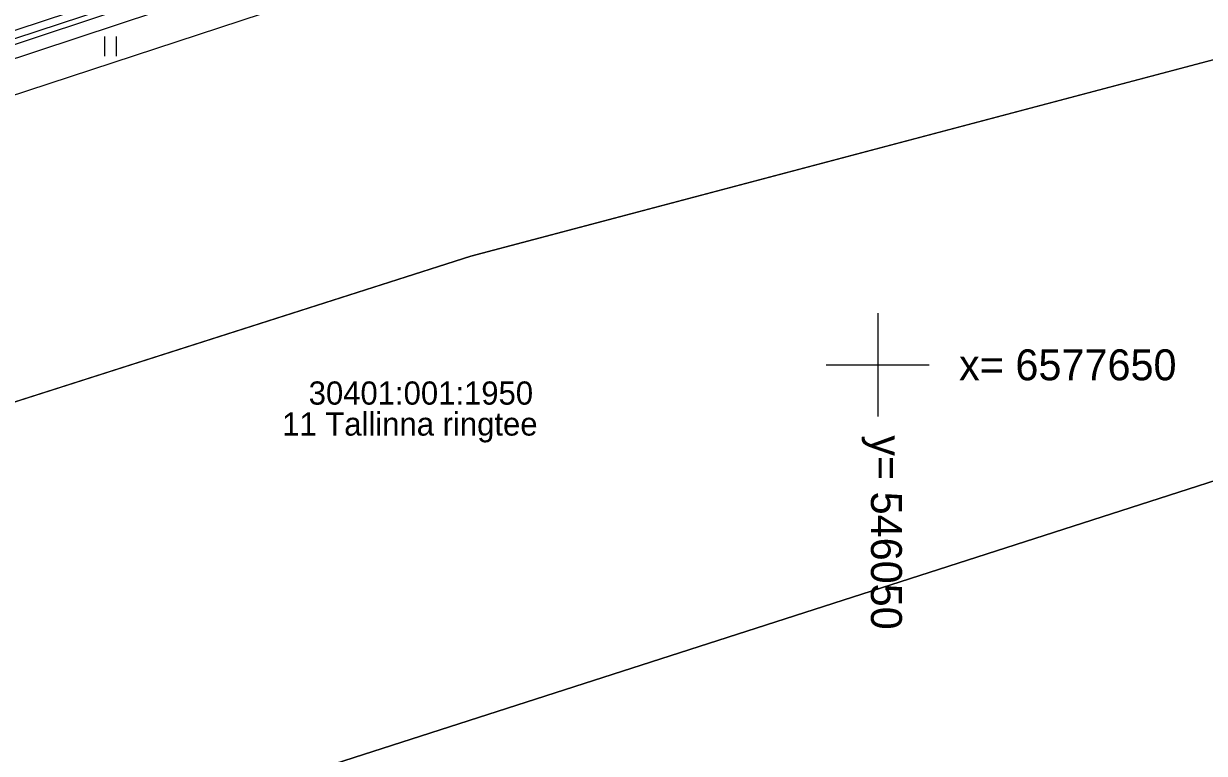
# Model space of a CAD drawing. Extents: x 543497 to 552146, y 6567125 to 6579845.
# Drawn here: x 546016.89 to 546062.67, y 6577634.93 to 6577663.23 of the extents above; entities that cross this region are included whole.
import ezdxf

# ---------------------------------------------------------------- set-up
doc = ezdxf.new("R2010")
doc.units = 0
for name, color, linetype in [('xref_Kangru tee 1_geodeesia$0$HALJASTUS', 7, 'Continuous'), ('xref_Kangru tee 1_geodeesia$0$Liiklus', 7, 'Continuous'), ('xref_Kangru tee 1_geodeesia$0$MOOTPIIR', 7, 'Continuous'), ('xref_Kangru tee 1_geodeesia$0$PIIR', 7, 'Continuous'), ('xref_Kangru tee 1_geodeesia$0$TEE', 7, 'Continuous'), ('xref_Kangru tee 1_geodeesia$0$vork', 7, 'Continuous')]:
    doc.layers.add(name, color=color, linetype=linetype)

# ---------------------------------------------------------------- blocks, each defined once
blk = doc.blocks.new('xref_Kangru tee 1_geodeesia$0$hein')
for p, q in [((-0.455, 0.761), (-0.455, -0.761)), ((0.455, 0.761), (0.455, -0.761))]:
    blk.add_line(p, q)
blk = doc.blocks.new('xref_Kangru tee 1_geodeesia$0$VKORIS')
for p, q in [((0, 4), (0, -4)), ((-4, 0), (4, 0))]:
    blk.add_line(p, q)

msp = doc.modelspace()

# ---------------------------------------------------------------- linework, layer by layer
at = {"layer": 'xref_Kangru tee 1_geodeesia$0$Liiklus'}
for points in [[(545910.777, 6577625.663), (545933.969, 6577634.025), (545958.008, 6577642.491), (545978.611, 6577649.687), (546003.506, 6577658.099), (546027.939, 6577666.219), (546052.189, 6577674.015), (546074.504, 6577681.116), (546097.636, 6577688.197), (546120.931, 6577695.189), (546144.399, 6577702.07)], [(546144.547, 6577701.652), (546121.068, 6577694.663), (546097.922, 6577687.788), (546074.601, 6577680.633), (546052.33, 6577673.558), (546028.25, 6577665.754), (546003.455, 6577657.552), (545979.103, 6577649.278), (545958.136, 6577642.016), (545934.298, 6577633.553), (545911.013, 6577625.148)]]:
    msp.add_lwpolyline(points, dxfattribs=at)
at = {"layer": 'xref_Kangru tee 1_geodeesia$0$MOOTPIIR'}
msp.add_lwpolyline([(545958.425, 6577640.634), (545979.717, 6577647.979), (546003.803, 6577656.298), (546028.634, 6577664.448), (546052.642, 6577672.359), (546075.012, 6577679.254), (546098.282, 6577686.38), (546121.547, 6577693.442), (546145.064, 6577700.183), (546144.756, 6577701.079), (546144.547, 6577701.652), (546144.399, 6577702.07), (546144.343, 6577702.205), (546144.19, 6577702.591), (546142.487, 6577707.254), (546140.733, 6577712.948), (546140.387, 6577713.403), (546140.081, 6577713.851), (546139.866, 6577714.146), (546138.846, 6577717.098), (546138.679, 6577717.517), (546137.781, 6577720.873), (546135.39, 6577726.178), (546132.125, 6577738.465)], dxfattribs=at)
at = {"layer": 'xref_Kangru tee 1_geodeesia$0$PIIR'}
for points in [[(546508.03, 6577841.48), (546527.76, 6577842.6), (546535.64, 6577829.79), (546540.71, 6577817.81), (546551.12, 6577809.99), (546561.59, 6577802.16), (546622.52, 6577814.88), (546633.51, 6577792.62), (546608.95, 6577787.91), (546573.78, 6577780.87), (546521.59, 6577770.69), (546316.12, 6577725.86), (546173.38, 6577691.06), (546034.23, 6577654.21), (545899.95, 6577611.29), (545780.54, 6577566.57), (545623.97, 6577499.02), (545555.77, 6577467.67), (545385.83, 6577376.92), (545249.19, 6577295.85), (545250.22, 6577289.9), (544980.83, 6577118.49)], [(545903.63, 6577591.56), (545899.95, 6577611.29), (546034.23, 6577654.21), (546173.38, 6577691.06), (546316.18, 6577725.87), (546317.36, 6577716.48), (546175.86, 6577681.83), (545957.87, 6577611.65), (545903.63, 6577591.56)], [(545920.45, 6577499.53), (545903.63, 6577591.56), (545957.87, 6577611.65), (546175.86, 6577681.83), (546317.36, 6577716.48), (546327.18, 6577637.77), (546148.98, 6577572.67), (545920.45, 6577499.53)]]:
    msp.add_lwpolyline(points, dxfattribs=at)
at = {"layer": 'xref_Kangru tee 1_geodeesia$0$TEE'}
for points in [[(545910.584, 6577626.12), (545933.661, 6577634.352), (545957.791, 6577642.935), (545978.471, 6577649.978), (546003.394, 6577658.646), (546027.796, 6577666.689), (546052.06, 6577674.499), (546074.348, 6577681.538), (546097.453, 6577688.664), (546120.761, 6577695.678), (546144.19, 6577702.591)], [(546144.343, 6577702.205), (546120.903, 6577695.427), (546097.566, 6577688.331), (546074.414, 6577681.298), (546052.115, 6577674.191), (546027.872, 6577666.376), (546003.492, 6577658.359), (545978.595, 6577649.764), (545957.931, 6577642.653), (545933.808, 6577634.136), (545910.722, 6577625.792)]]:
    msp.add_lwpolyline(points, dxfattribs=at)

# ---------------------------------------------------------------- block references
at = {"layer": 'xref_Kangru tee 1_geodeesia$0$HALJASTUS', "xscale": 0.5, "yscale": 0.5}
msp.add_blockref('xref_Kangru tee 1_geodeesia$0$hein', (546020.248, 6577662.349), dxfattribs=at)
at = {"layer": 'xref_Kangru tee 1_geodeesia$0$vork', "xscale": 0.5, "yscale": 0.5}
msp.add_blockref('xref_Kangru tee 1_geodeesia$0$VKORIS', (546050, 6577650), dxfattribs=at)

# ---------------------------------------------------------------- texts
at = {"layer": 'xref_Kangru tee 1_geodeesia$0$PIIR'}
for s, p in [('30401:001:1950', (546027.939, 6577648.455)), ('11 Tallinna ringtee', (546026.911, 6577647.255))]:
    msp.add_text(s, height=0.9, dxfattribs=at).set_placement(p)
at = {"layer": 'xref_Kangru tee 1_geodeesia$0$vork'}
msp.add_text('x= 6577650', height=1.2, dxfattribs=at).set_placement((546053.153, 6577649.4))
msp.add_text('y= 546050', height=1.2, rotation=270, dxfattribs=at).set_placement((546049.739, 6577647.266))

doc.saveas('drawing.dxf')
